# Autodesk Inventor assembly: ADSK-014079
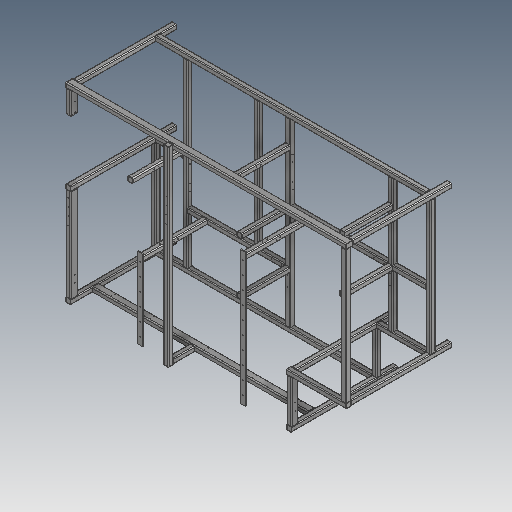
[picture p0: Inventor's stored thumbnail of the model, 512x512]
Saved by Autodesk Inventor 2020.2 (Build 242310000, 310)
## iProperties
_FrameDoc: Frame Assembly
_Version: 15.0.0
Part Number: ADSK-014079
Description: Phantom-Baugruppe
Document SubType Name: Baugruppe
Designer: lutzd
Mass: 272688 g
Surface Area: 134499 cm^2
Volume: 34737.4 cm^3
Density: 7.85 g/cm^3
DocNumber: ADSK-014079
Folder: .
Dimensions: 2027x1065x2690 mm
Mass: 272,688 kg
Title: Gestellbaugruppen
Author: lutzd
Revision Number: -
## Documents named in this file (57)
- D:\07 - DEMODATEN\OTX 2019 - Dataset - UPDATE - Dez2019\Designs\07-Packing machine\ADSK-014078\Frame\ADSK-014079.iam
- D:\07 - DEMODATEN\OTX 2019 - Dataset - UPDATE - Dez2019\Designs\07-Packing machine\ADSK-014078\Frame\ADSK-014105.ipt
- D:\07 - DEMODATEN\OTX 2019 - Dataset - UPDATE - Dez2019\Designs\07-Packing machine\ADSK-014078\Frame\ADSK-014139.ipt
- D:\07 - DEMODATEN\OTX 2019 - Dataset - UPDATE - Dez2019\Designs\07-Packing machine\ADSK-014078\Frame\ADSK-014136.ipt
- D:\07 - DEMODATEN\OTX 2019 - Dataset - UPDATE - Dez2019\Designs\07-Packing machine\ADSK-014078\Frame\ADSK-014135.ipt
- D:\07 - DEMODATEN\OTX 2019 - Dataset - UPDATE - Dez2019\Designs\07-Packing machine\ADSK-014078\Frame\ADSK-014134.ipt
- D:\07 - DEMODATEN\OTX 2019 - Dataset - UPDATE - Dez2019\Designs\07-Packing machine\ADSK-014078\Frame\ADSK-014133.ipt
- D:\07 - DEMODATEN\OTX 2019 - Dataset - UPDATE - Dez2019\Designs\07-Packing machine\ADSK-014078\Frame\ADSK-014106.ipt
- D:\07 - DEMODATEN\OTX 2019 - Dataset - UPDATE - Dez2019\Designs\07-Packing machine\ADSK-014078\Frame\ADSK-014107.ipt
- D:\07 - DEMODATEN\OTX 2019 - Dataset - UPDATE - Dez2019\Designs\07-Packing machine\ADSK-014078\Frame\ADSK-014108.ipt
- D:\07 - DEMODATEN\OTX 2019 - Dataset - UPDATE - Dez2019\Designs\07-Packing machine\ADSK-014078\Frame\ADSK-014109.ipt
- D:\07 - DEMODATEN\OTX 2019 - Dataset - UPDATE - Dez2019\Designs\07-Packing machine\ADSK-014078\Frame\ADSK-014110.ipt
- D:\07 - DEMODATEN\OTX 2019 - Dataset - UPDATE - Dez2019\Designs\07-Packing machine\ADSK-014078\Frame\ADSK-014111.ipt
- D:\07 - DEMODATEN\OTX 2019 - Dataset - UPDATE - Dez2019\Designs\07-Packing machine\ADSK-014078\Frame\ADSK-014112.ipt
- D:\07 - DEMODATEN\OTX 2019 - Dataset - UPDATE - Dez2019\Designs\07-Packing machine\ADSK-014078\Frame\ADSK-014113.ipt
- D:\07 - DEMODATEN\OTX 2019 - Dataset - UPDATE - Dez2019\Designs\07-Packing machine\ADSK-014078\Frame\ADSK-014114.ipt
- D:\07 - DEMODATEN\OTX 2019 - Dataset - UPDATE - Dez2019\Designs\07-Packing machine\ADSK-014078\Frame\ADSK-014115.ipt
- D:\07 - DEMODATEN\OTX 2019 - Dataset - UPDATE - Dez2019\Designs\07-Packing machine\ADSK-014078\Frame\ADSK-014116.ipt
- D:\07 - DEMODATEN\OTX 2019 - Dataset - UPDATE - Dez2019\Designs\07-Packing machine\ADSK-014078\Frame\ADSK-014117.ipt
- D:\07 - DEMODATEN\OTX 2019 - Dataset - UPDATE - Dez2019\Designs\07-Packing machine\ADSK-014078\Frame\ADSK-014118.ipt
- D:\07 - DEMODATEN\OTX 2019 - Dataset - UPDATE - Dez2019\Designs\07-Packing machine\ADSK-014078\Frame\ADSK-014119.ipt
- D:\07 - DEMODATEN\OTX 2019 - Dataset - UPDATE - Dez2019\Designs\07-Packing machine\ADSK-014078\Frame\ADSK-014120.ipt
- D:\07 - DEMODATEN\OTX 2019 - Dataset - UPDATE - Dez2019\Designs\07-Packing machine\ADSK-014078\Frame\ADSK-014122.ipt
- D:\07 - DEMODATEN\OTX 2019 - Dataset - UPDATE - Dez2019\Designs\07-Packing machine\ADSK-014078\Frame\ADSK-014123.ipt
- D:\07 - DEMODATEN\OTX 2019 - Dataset - UPDATE - Dez2019\Designs\07-Packing machine\ADSK-014078\Frame\ADSK-014124.ipt
- D:\07 - DEMODATEN\OTX 2019 - Dataset - UPDATE - Dez2019\Designs\07-Packing machine\ADSK-014078\Frame\ADSK-014125.ipt
- D:\07 - DEMODATEN\OTX 2019 - Dataset - UPDATE - Dez2019\Designs\07-Packing machine\ADSK-014078\Frame\ADSK-014126.ipt
- D:\07 - DEMODATEN\OTX 2019 - Dataset - UPDATE - Dez2019\Designs\07-Packing machine\ADSK-014078\Frame\ADSK-014127.ipt
- D:\07 - DEMODATEN\OTX 2019 - Dataset - UPDATE - Dez2019\Designs\07-Packing machine\ADSK-014078\Frame\ADSK-014128.ipt
- D:\07 - DEMODATEN\OTX 2019 - Dataset - UPDATE - Dez2019\Designs\07-Packing machine\ADSK-014078\Frame\ADSK-014129.ipt
- D:\07 - DEMODATEN\OTX 2019 - Dataset - UPDATE - Dez2019\Designs\07-Packing machine\ADSK-014078\Frame\ADSK-014149.ipt
- D:\07 - DEMODATEN\OTX 2019 - Dataset - UPDATE - Dez2019\Designs\07-Packing machine\ADSK-014078\Frame\ADSK-014148.ipt
- D:\07 - DEMODATEN\OTX 2019 - Dataset - UPDATE - Dez2019\Designs\07-Packing machine\ADSK-014078\Frame\ADSK-014147.ipt
- D:\07 - DEMODATEN\OTX 2019 - Dataset - UPDATE - Dez2019\Designs\07-Packing machine\ADSK-014078\Frame\ADSK-014146.ipt
- D:\07 - DEMODATEN\OTX 2019 - Dataset - UPDATE - Dez2019\Designs\07-Packing machine\ADSK-014078\Frame\ADSK-014145.ipt
- D:\07 - DEMODATEN\OTX 2019 - Dataset - UPDATE - Dez2019\Designs\07-Packing machine\ADSK-014078\Frame\ADSK-014144.ipt
- D:\07 - DEMODATEN\OTX 2019 - Dataset - UPDATE - Dez2019\Designs\07-Packing machine\ADSK-014078\Frame\ADSK-014143.ipt
- D:\07 - DEMODATEN\OTX 2019 - Dataset - UPDATE - Dez2019\Designs\07-Packing machine\ADSK-014078\Frame\ADSK-014142.ipt
- D:\07 - DEMODATEN\OTX 2019 - Dataset - UPDATE - Dez2019\Designs\07-Packing machine\ADSK-014078\Frame\ADSK-014141.ipt
- D:\07 - DEMODATEN\OTX 2019 - Dataset - UPDATE - Dez2019\Designs\07-Packing machine\ADSK-014078\Frame\ADSK-014140.ipt
- D:\07 - DEMODATEN\OTX 2019 - Dataset - UPDATE - Dez2019\Designs\07-Packing machine\ADSK-014078\Frame\ADSK-014151.ipt
- D:\07 - DEMODATEN\OTX 2019 - Dataset - UPDATE - Dez2019\Designs\07-Packing machine\ADSK-014078\Frame\ADSK-014150.ipt
- D:\07 - DEMODATEN\OTX 2019 - Dataset - UPDATE - Dez2019\Designs\07-Packing machine\Parts\ADSK-014166.ipt
- D:\07 - DEMODATEN\OTX 2019 - Dataset - UPDATE - Dez2019\Designs\07-Packing machine\Parts\ADSK-014165.ipt
- D:\07 - DEMODATEN\OTX 2019 - Dataset - UPDATE - Dez2019\Designs\07-Packing machine\Parts\ADSK-014164.ipt
- D:\07 - DEMODATEN\OTX 2019 - Dataset - UPDATE - Dez2019\Designs\07-Packing machine\Parts\ADSK-014163.ipt
- D:\07 - DEMODATEN\OTX 2019 - Dataset - UPDATE - Dez2019\Designs\07-Packing machine\Parts\ADSK-014162.ipt
- D:\07 - DEMODATEN\OTX 2019 - Dataset - UPDATE - Dez2019\Designs\07-Packing machine\Parts\ADSK-014161.ipt
- D:\07 - DEMODATEN\OTX 2019 - Dataset - UPDATE - Dez2019\Designs\07-Packing machine\Parts\ADSK-014160.ipt
- D:\07 - DEMODATEN\OTX 2019 - Dataset - UPDATE - Dez2019\Designs\07-Packing machine\Parts\ADSK-014159.ipt
- D:\07 - DEMODATEN\OTX 2019 - Dataset - UPDATE - Dez2019\Designs\07-Packing machine\Parts\ADSK-014158.ipt
- D:\07 - DEMODATEN\OTX 2019 - Dataset - UPDATE - Dez2019\Designs\07-Packing machine\Parts\ADSK-014157.ipt
- D:\07 - DEMODATEN\OTX 2019 - Dataset - UPDATE - Dez2019\Designs\07-Packing machine\Parts\ADSK-014156.ipt
- D:\07 - DEMODATEN\OTX 2019 - Dataset - UPDATE - Dez2019\Designs\07-Packing machine\Parts\ADSK-014155.ipt
- D:\07 - DEMODATEN\OTX 2019 - Dataset - UPDATE - Dez2019\Designs\07-Packing machine\Parts\ADSK-014154.ipt
- D:\07 - DEMODATEN\OTX 2019 - Dataset - UPDATE - Dez2019\Designs\07-Packing machine\Parts\ADSK-014153.ipt
- D:\07 - DEMODATEN\OTX 2019 - Dataset - UPDATE - Dez2019\Designs\07-Packing machine\Parts\ADSK-014152.ipt
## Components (56 placed, 8 different names)
1. Gestellreferenzmodell
2. DIN 50 x 50 x 5:30
3. DIN 50 x 50 x 5:30
4. DIN 50 x 50 x 5:30
5. DIN 50 x 50 x 5:30
6. DIN 50 x 50 x 5:30
7. DIN 50 x 50 x 5:30
8. DIN 50 x 50 x 5:30
9. DIN 50 x 50 x 5:30
10. DIN 50 x 50 x 5:30
11. DIN 50 x 50 x 5:30
12. DIN 50 x 50 x 5:30
13. DIN 50 x 50 x 5:30
14. DIN 50 x 50 x 5:30
15. DIN 50 x 50 x 5:30
16. DIN 50 x 50 x 5:30
17. DIN 50 x 50 x 5:30
18. DIN 50 x 50 x 5:30
19. DIN 50 x 50 x 5:30
20. DIN 50 x 50 x 5:30
21. DIN 50 x 50 x 5:30
22. DIN 50 x 50 x 5:30
23. DIN 50 x 50 x 5:30
24. DIN 50 x 50 x 5:30
25. DIN 50 x 50 x 5:26
26. DIN 70 x 50 x 5:1
27. DIN 70 x 50 x 5:2
28. DIN 70 x 50 x 5:3
29. DIN 50 x 50 x 6,3:29
30. DIN 70 x 50 x 5:4
31. DIN 50 x 50 x 5:31
32. DIN 50 x 50 x 5:32
33. DIN 70 x 50 x 5:5
34. DIN 50 x 50 x 5:33
35. DIN 50 x 50 x 5:34
36. DIN 50 x 50 x 5:35
37. DIN 50 x 50 x 5:36
38. DIN 50 x 10:1
39. DIN 50 x 10:2
40. DIN 50 x 50 x 5:37
41. DIN 50 x 50 x 5:38
42. Gerundete Ecken (mm) 5 x 60 x 40:1
43. Gerundete Ecken (mm) 5 x 60 x 40:2
44. Gerundete Ecken (mm) 5 x 60 x 40:3
45. Gerundete Ecken (mm) 5 x 39,384472 x 39,384472:1
46. Gerundete Ecken (mm) 5 x 39,384472 x 39,384472:2
47. Gerundete Ecken (mm) 5 x 39,384472 x 39,384472:3
48. Gerundete Ecken (mm) 5 x 39,384472 x 39,384472:4
49. Gerundete Ecken (mm) 5 x 39,384472 x 39,384472:5
50. Gerundete Ecken (mm) 5 x 39,384472 x 39,384472:6
51. Gerundete Ecken (mm) 5 x 39,384472 x 39,384472:7
52. Gerundete Ecken (mm) 5 x 39,384472 x 39,384472:8
53. Gerundete Ecken (mm) 5 x 39,384472 x 39,384472:9
54. Gerundete Ecken (mm) 5 x 36,624435 x 36,624435:1
55. Gerundete Ecken (mm) 5 x 39,384472 x 39,384472:10
56. Gerundete Ecken (mm) 5 x 39,384472 x 39,384472:11
